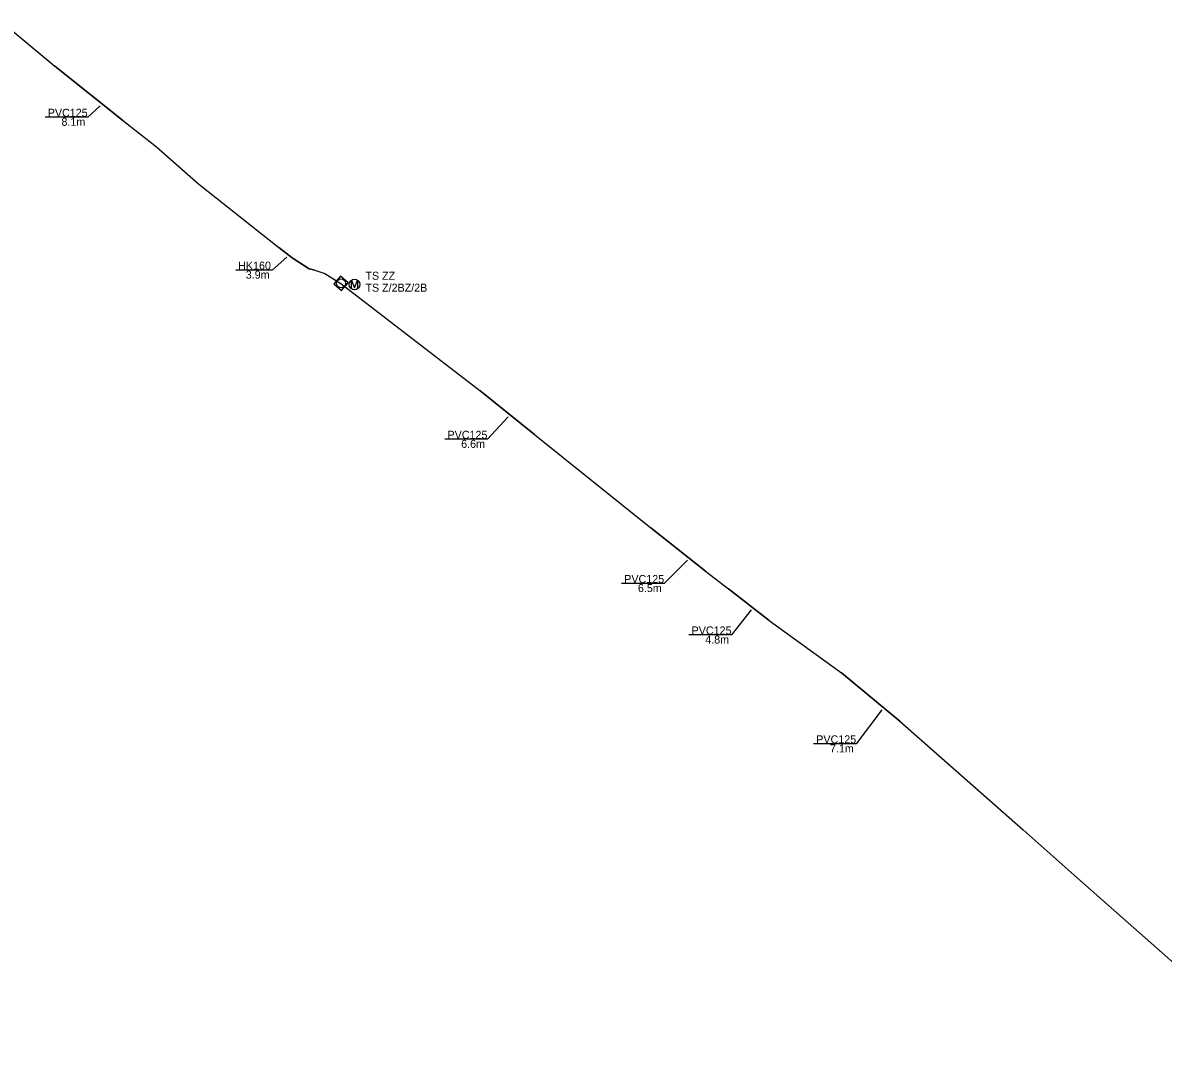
# Model space of a CAD drawing. Extents: x -594469 to -594054, y -1167536 to -1167142.
# Drawn here: x -594368.7 to -594261.8, y -1167310.5 to -1167214.9 of the extents above; entities that cross this region are included whole.
import ezdxf

# ---------------------------------------------------------------- set-up
doc = ezdxf.new("R2010")
doc.units = 0
for name, color, linetype in [('Vrstva 1', 7, 'Continuous'), ('Vrstva 17', 7, 'Continuous'), ('Vrstva 19', 7, 'Continuous'), ('Vrstva 5', 7, 'Continuous'), ('Vrstva 52', 7, 'Continuous'), ('Vrstva 6', 7, 'Continuous'), ('Vrstva 60', 7, 'Continuous')]:
    doc.layers.add(name, color=color, linetype=linetype)

msp = doc.modelspace()

# ---------------------------------------------------------------- linework, layer by layer
at = {"layer": 'Vrstva 1'}
for points in [[(-594370.54, -1167214.93), (-594365.67, -1167219), (-594359.33, -1167224.05), (-594356.13, -1167226.55), (-594352.2, -1167230.03), (-594344.68, -1167235.97), (-594343.45, -1167236.95), (-594341.85, -1167237.98), (-594341.41, -1167238.08), (-594340.36, -1167238.4), (-594338.86, -1167239.34)], [(-594338.86, -1167239.34), (-594325.84, -1167249.36), (-594320.73, -1167253.51), (-594309.84, -1167262.24), (-594304.71, -1167266.3), (-594302.55, -1167267.96), (-594298.75, -1167270.91), (-594291.96, -1167275.84), (-594286.5, -1167280.36), (-594274.94, -1167290.52), (-594270.17, -1167294.78), (-594252.34, -1167310.52)]]:
    msp.add_lwpolyline(points, dxfattribs=at)
at = {"layer": 'Vrstva 17'}
msp.add_lwpolyline([(-594338.82, -1167240.02), (-594338.18, -1167239.3), (-594338.9, -1167238.66), (-594339.54, -1167239.38)], close=True, dxfattribs=at)
msp.add_circle((-594338.86, -1167239.34), 0.432, dxfattribs=at)
at = {"layer": 'Vrstva 5'}
for points in [[(-594359.33, -1167224.05), (-594365.67, -1167219)], [(-594341.41, -1167238.08), (-594341.85, -1167237.98), (-594343.45, -1167236.95), (-594344.68, -1167235.97)], [(-594320.73, -1167253.51), (-594325.84, -1167249.36)], [(-594304.71, -1167266.3), (-594309.84, -1167262.24)], [(-594298.75, -1167270.91), (-594302.55, -1167267.96)], [(-594286.5, -1167280.36), (-594291.96, -1167275.84)]]:
    msp.add_lwpolyline(points, dxfattribs=at)
at = {"layer": 'Vrstva 52'}
for points in [[(-594337.86, -1167239.81), (-594337.86, -1167239.07)], [(-594337.86, -1167239.07), (-594337.59, -1167239.77)], [(-594337.59, -1167239.77), (-594337.32, -1167239.07)], [(-594337.32, -1167239.07), (-594337.32, -1167239.81)]]:
    msp.add_lwpolyline(points, dxfattribs=at)
msp.add_circle((-594337.59, -1167239.44), 0.5, dxfattribs=at)
at = {"layer": 'Vrstva 60'}
for p, q in [((-594361.42, -1167222.71), (-594362.59, -1167223.78)), ((-594362.59, -1167223.78), (-594366.59, -1167223.78)), ((-594343.92, -1167236.9), (-594345.32, -1167238.1)), ((-594345.32, -1167238.1), (-594348.72, -1167238.1)), ((-594323.19, -1167251.83), (-594325.14, -1167253.95)), ((-594325.14, -1167253.95), (-594329.14, -1167253.95)), ((-594306.41, -1167265.27), (-594308.58, -1167267.46)), ((-594308.58, -1167267.46), (-594312.58, -1167267.46)), ((-594300.44, -1167269.92), (-594302.28, -1167272.28)), ((-594302.28, -1167272.28), (-594306.28, -1167272.28)), ((-594288.19, -1167279.28), (-594290.59, -1167282.48)), ((-594290.59, -1167282.48), (-594294.59, -1167282.48))]:
    msp.add_line(p, q, dxfattribs=at)

# ---------------------------------------------------------------- texts
at = {"layer": 'Vrstva 19'}
for s, p in [('TS ZZ', (-594336.57, -1167239)), ('TS Z/2BZ/2B', (-594336.57, -1167240.12))]:
    msp.add_text(s, height=0.75, dxfattribs=at).set_placement(p)
at = {"layer": 'Vrstva 6'}
for s, p in [('PVC125', (-594366.33, -1167223.73)), ('8.1m', (-594365.05, -1167224.58)), ('HK160', (-594348.49, -1167238.05)), ('3.9m', (-594347.78, -1167238.9)), ('PVC125', (-594328.88, -1167253.9)), ('6.6m', (-594327.6, -1167254.75)), ('PVC125', (-594312.32, -1167267.41)), ('6.5m', (-594311.04, -1167268.26)), ('PVC125', (-594306.01, -1167272.23)), ('4.8m', (-594304.73, -1167273.08)), ('PVC125', (-594294.33, -1167282.43)), ('7.1m', (-594293.05, -1167283.28))]:
    msp.add_text(s, height=0.75, dxfattribs=at).set_placement(p)

doc.saveas('drawing.dxf')
